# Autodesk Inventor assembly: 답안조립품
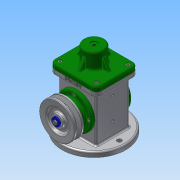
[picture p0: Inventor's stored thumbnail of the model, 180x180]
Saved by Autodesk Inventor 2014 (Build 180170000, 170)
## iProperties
Created: 2018-10
Part Number: 답안조립품
Document SubType Name: Assembly
Designer: Administrator
Author: Administrator
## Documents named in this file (18)
- C:\Users\Administrator\Desktop\481007V1008\답안조립품.iam
- C:\Users\Administrator\Desktop\481007V1008\본체.ipt
- C:\Users\Administrator\Desktop\481007V1008\E-링.ipt
- C:\Users\Administrator\Desktop\481007V1008\V-벨트풀리.ipt
- C:\Users\Administrator\Desktop\481007V1008\덮개.ipt
- C:\Users\Administrator\Desktop\481007V1008\뒤커버.ipt
- C:\Users\Administrator\Desktop\481007V1008\링크.ipt
- C:\Users\Administrator\Desktop\481007V1008\베어링 17 x 40 x 12.ipt
- C:\Users\Administrator\Desktop\481007V1008\볼트 M4 x 8.ipt
- C:\Users\Administrator\Desktop\481007V1008\볼트 M4 x 10.ipt
- C:\Users\Administrator\Desktop\481007V1008\슬라이더.ipt
- C:\Users\Administrator\Desktop\481007V1008\앞커버.ipt
- C:\Users\Administrator\Desktop\481007V1008\오일 실 17 30 8.ipt
- C:\Users\Administrator\Desktop\481007V1008\와셔 4x16.ipt
- C:\Users\Administrator\Desktop\481007V1008\클레비스 핀 6 x 22.ipt
- 클레비스 핀 6 x 22.ipt
- C:\Users\Administrator\Desktop\481007V1008\키 4 x 4 x 12.ipt
- C:\Users\Administrator\Desktop\481007V1008\편심축.ipt
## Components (2 placed, 2 different names)
1. E-링:1 — 각도:1
2. V-벨트풀리:1 — 각도:10
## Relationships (2: Angle 2)
- 각도:1 [Angle]: E-링:1
- 각도:10 [Angle]: V-벨트풀리:1
